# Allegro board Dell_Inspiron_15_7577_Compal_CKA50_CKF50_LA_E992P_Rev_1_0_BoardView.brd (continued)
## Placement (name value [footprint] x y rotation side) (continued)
PC5588  .1U_0402_16V7K  [C_0402]  173.48 108.23 180 bottom
PC5589  .1U_0402_16V7K  [C_0402]  173.49 107.31 180 bottom
PC5590  1U_0402_6.3V6K  [C_0402]  150.87 98.08 0 top
PC5591  1U_0402_6.3V6K  [C_0402]  146.68 98.14 0 top
PC5592  1U_0402_6.3V6K  [C_0402]  146.68 97.2 0 top
PC5593  1U_0402_6.3V6K  [C_0402]  150.54 87.67 0 top
PC5594  1U_0402_6.3V6K  [C_0402]  148.7 87.62 0 top
PC5595  1U_0402_6.3V6K  [C_0402]  148.71 98.08 0 top
PC5596  .1U_0402_16V7K  [C_0402]  148.71 97.14 0 top
PC5597  .1U_0402_16V7K  [C_0402]  158.05 87.62 0 top
PC5598  .1U_0402_16V7K  [C_0402]  156.2 87.62 0 top
PC5599  .1U_0402_16V7K  [C_0402]  157.22 98.14 0 top
PC5600  .1U_0402_16V7K  [C_0402]  152.97 97.14 0 top
PC5601  .1U_0402_16V7K  [C_0402]  152.45 87.7 0 top
PC5602  .1U_0402_16V7K  [C_0402]  154.35 87.69 0 top
PC5603  .1U_0402_16V7K  [C_0402]  157.22 97.14 0 top
PC5604  .1U_0402_16V7K  [C_0402]  152.97 98.08 0 top
PC5605  .1U_0402_16V7K  [C_0402]  159.19 98.8 0 top
PC5606  .1U_0402_16V7K  [C_0402]  159.19 97.72 0 top
PC5607  .1U_0402_16V7K  [C_0402]  155.12 97.14 0 top
PC5608  .1U_0402_16V7K  [C_0402]  155.12 98.14 0 top
PC5609  .1U_0402_16V7K  [C_0402]  146.73 87.69 0 top
PC5610  .1U_0402_16V7K  [C_0402]  150.87 97.14 0 top
PC6000  0.1U_0402_25V6  [C_0402]  152.19 136.6 90 top
PC6002  0.01U_0402_16V7K  [C_0402]  153.06 136.73 0 top
PC6006  0.015U_0402_16V7K  [C_0402]  153.52 135.08 90 bottom
PC6007  0.12U_0402_10V6K  [C_0402]  149.53 142.49 90 top
PC6008  0.1U_0402_25V6  [C_0402]  153.06 134.93 0 top
PC6009  0.1U_0402_10V6K  [C_0402]  150.36 144.31 0 top
PC6011  0.1U_0402_25V6  [C_0402]  152.92 132.67 90 top
PC6014  1U_0402_6.3V6K  [C_0402]  161.32 142.65 0 top
PC6015  4700P_0402_50V7K  [C_0402]  164.36 135.6 0 top
PC6016  0.01U_0402_16V  [C_0402]  163.5 137.43 180 top
PC6100  1U_0603_16V7  [C_0603]  170.41 131.16 180 bottom
PC6101  1U_0603_16V7  [C_0603]  177.52 128.87 90 top
PC6102  0.1U_0603_50V7K  [C_0603]  170.09 133.25 0 bottom
PC6103  10U_0805_25V6K~D  [C_0805]  172.84 134.39 180 top
PC6104  10U_0805_25V6K~D  [C_0805]  172.84 136.11 180 top
PC6105  10U_0805_25V6K~D  [C_0805]  173.6 143.44 0 top
PC6106  100U_25V_M  [C_ECST250ADA101MF611]  164.6 141.32 0 bottom
PC6107  470U_D2_2VM_R4.5M~D  [C_D1]  189.14 130.9 0 bottom
PC6108  1U_0402_25V6K  [C_0402]  166.21 130.33 0 bottom
PC6109  1000P_0402_50V7K  [C_0402]  166.21 131.22 0 bottom
PC6110  0.1U_0402_25V6  [C_0402]  172.84 132.11 180 top
PC6111  2200P_0402_50V7K  [C_0402]  172.82 133.06 180 top
PC6112  10U_0805_25V6K~D  [C_0805]  173.94 135.98 0 bottom
PC6113  3300P_0805_50V7K  [C_0805]  178 132.81 0 top
PC6114  1U_0603_16V7  [C_0603]  170.03 139.99 180 bottom
PC6115  0.1U_0603_50V7K  [C_0603]  169.5 142.38 0 bottom
PC6116  1U_0603_16V7  [C_0603]  176.32 137.76 90 top
PC6117  0.1U_0402_25V6  [C_0402]  172.26 140.05 180 top
PC6118  2200P_0402_50V7K  [C_0402]  172.25 141 180 top
PC6119  10U_0805_25V6K~D  [C_0805]  172.44 142.38 180 top
PC6121  470U_D2_2VM_R4.5M~D  [C_D1]  191.49 116.11 90 bottom
PC6122  1U_0402_25V6K  [C_0402]  167.74 142.65 0 top
PC6123  1000P_0402_50V7K  [C_0402]  167.74 143.54 0 top
PC6124  10U_0805_25V6K~D  [C_0805]  173.99 135.98 0 top
PC6125  10U_0805_25V6K~D  [C_0805]  177.72 144.71 180 bottom
PC6126  10U_0805_25V6K~D  [C_0805]  175.59 123.42 0 top
PC6127  3300P_0805_50V7K  [C_0805]  179.13 142.28 270 top
PC6128  1U_0603_16V7  [C_0603]  171.69 117.86 90 bottom
PC6129  0.1U_0603_50V7K  [C_0603]  171.79 121.28 0 bottom
PC6130  1U_0603_16V7  [C_0603]  176.44 115.15 180 bottom
PC6131  1U_0402_25V6K  [C_0402]  176.49 126.46 0 top
PC6132  1000P_0402_50V7K  [C_0402]  167.09 139.98 0 top
PC6133  0.1U_0402_25V6  [C_0402]  167.1 140.96 0 top
PC6134  2200P_0402_50V7K  [C_0402]  176.49 127.35 0 top
PC6135  10U_0805_25V6K~D  [C_0805]  173.2 144.71 0 bottom
PC6136  10U_0805_25V6K~D  [C_0805]  175.59 125.12 0 top
PC6137  10U_0805_25V6K~D  [C_0805]  175.59 123.42 0 bottom
PC6138  10U_0805_25V6K~D  [C_0805]  175.59 125.12 0 bottom
PC6140  470U_D2_2VM_R4.5M~D  [C_D1]  188.94 135.66 0 bottom
PC6141  3300P_0805_50V7K  [C_0805]  179.81 118.87 90 top
PC6500  1U_0402_6.3V6K  [C_0402]  215.71 91.91 180 top
PC6501  1U_0402_6.3V6K  [C_0402]  215.71 93.31 180 top
PC6502  1U_0402_6.3V6K  [C_0402]  212.57 105.18 180 top
PC6503  1U_0402_6.3V6K  [C_0402]  210.99 106.58 0 top
PC6504  1U_0402_6.3V6K  [C_0402]  224.46 96.8 180 top
PC6505  1U_0402_6.3V6K  [C_0402]  217.48 91.91 180 top
PC6506  1U_0402_6.3V6K  [C_0402]  213.39 105.18 0 top
PC6507  1U_0402_6.3V6K  [C_0402]  217.36 90.51 180 top
PC6508  1U_0402_6.3V6K  [C_0402]  215.57 90.51 180 top
PC6509  1U_0402_6.3V6K  [C_0402]  212.88 90.52 0 top
PC6510  1U_0402_6.3V6K  [C_0402]  213.03 91.91 0 top
PC6511  1U_0402_6.3V6K  [C_0402]  220.12 93.31 0 top
PC6512  1U_0402_6.3V6K  [C_0402]  218.34 93.31 0 top
PC6513  1U_0402_6.3V6K  [C_0402]  217.48 93.31 180 top
PC6514  1U_0402_6.3V6K  [C_0402]  223.25 91.91 180 top
PC6515  1U_0402_6.3V6K  [C_0402]  223 93.31 180 top
PC6516  1U_0402_6.3V6K  [C_0402]  213.03 93.31 0 top
PC6517  1U_0402_6.3V6K  [C_0402]  213.03 94.7 0 top
PC6518  1U_0402_6.3V6K  [C_0402]  215.71 94.7 180 top
PC6519  1U_0402_6.3V6K  [C_0402]  227.76 93.95 270 top
PC6520  1U_0402_6.3V6K  [C_0402]  210.78 105.31 270 top
PC6521  1U_0402_6.3V6K  [C_0402]  197.54 112.64 180 top
PC6522  1U_0402_6.3V6K  [C_0402]  215.63 105.18 0 top
PC6523  1U_0402_6.3V6K  [C_0402]  210.36 108.03 90 top
PC6524  1U_0402_6.3V6K  [C_0402]  208.24 110.01 90 top
PC6525  1U_0402_6.3V6K  [C_0402]  204.38 113.36 90 top
PC6526  1U_0402_6.3V6K  [C_0402]  201.14 110.91 270 top
PC6527  1U_0402_6.3V6K  [C_0402]  215.8 98.14 0 top
PC6528  1U_0402_6.3V6K  [C_0402]  215.8 96.8 0 top
PC6529  1U_0402_6.3V6K  [C_0402]  209.47 109.87 90 top
PC6530  1U_0402_6.3V6K  [C_0402]  205.27 113.36 90 top
PC6531  1U_0402_6.3V6K  [C_0402]  203.49 113.36 90 top
PC6532  1U_0402_6.3V6K  [C_0402]  212.81 96.8 0 top
PC6533  1U_0402_6.3V6K  [C_0402]  210.55 98.2 180 top
PC6534  1U_0402_6.3V6K  [C_0402]  223.55 90.52 0 top
PC6535  1U_0402_6.3V6K  [C_0402]  223.95 88.49 180 top
PC6536  1U_0402_6.3V6K  [C_0402]  221.28 88.49 0 top
PC6537  1U_0402_6.3V6K  [C_0402]  222.68 89.82 180 top
PC6538  1U_0402_6.3V6K  [C_0402]  220 89.88 0 top
PC6539  1U_0402_6.3V6K  [C_0402]  218.22 89.88 0 top
PC6540  1U_0402_6.3V6K  [C_0402]  216.69 88.42 0 top
PC6541  1U_0402_6.3V6K  [C_0402]  211.96 88.35 180 top
PC6542  1U_0402_6.3V6K  [C_0402]  210.3 90.52 180 top
PC6543  1U_0402_6.3V6K  [C_0402]  210.37 91.91 180 top
PC6544  1U_0402_6.3V6K  [C_0402]  210.37 93.31 180 top
PC6545  1U_0402_6.3V6K  [C_0402]  210.37 94.7 180 top
PC6546  1U_0402_6.3V6K  [C_0402]  211.24 91.91 0 top
PC6547  1U_0402_6.3V6K  [C_0402]  211.24 93.31 0 top
PC6548  1U_0402_6.3V6K  [C_0402]  211.24 94.7 0 top
PC6549  1U_0402_6.3V6K  [C_0402]  224.47 103.09 180 top
PC6550  1U_0402_6.3V6K  [C_0402]  225.29 96.8 0 top
PC6551  1U_0402_6.3V6K  [C_0402]  225.32 104.49 0 top
PC6552  1U_0402_6.3V6K  [C_0402]  220.12 91.91 0 top
PC6553  1U_0402_6.3V6K  [C_0402]  224.46 98.2 180 top
PC6554  1U_0402_6.3V6K  [C_0402]  224.46 104.49 180 top
PC6555  1U_0402_6.3V6K  [C_0402]  212.05 90.52 180 top
PC6556  1U_0402_6.3V6K  [C_0402]  225.32 98.2 0 top
PC6557  1U_0402_6.3V6K  [C_0402]  218.34 91.91 0 top
PC6558  1U_0402_6.3V6K  [C_0402]  224.46 100.29 180 top
PC6559  1U_0402_6.3V6K  [C_0402]  224.47 101.69 180 top
PC6560  1U_0402_6.3V6K  [C_0402]  225.32 101.69 0 top
PC6561  1U_0402_6.3V6K  [C_0402]  225.35 100.29 0 top
PC6562  1U_0402_6.3V6K  [C_0402]  221.45 94.64 0 top
PC6563  1U_0402_6.3V6K  [C_0402]  220.59 94.64 180 top
PC6564  1U_0402_6.3V6K  [C_0402]  225.32 103.09 0 top
PC6565  10U_0603_6.3V6M  [C_0603]  197.09 121.82 90 bottom
PC6566  10U_0603_6.3V6M  [C_0603]  195.82 121.82 90 bottom
PC6567  10U_0603_6.3V6M  [C_0603]  194.55 121.82 90 bottom
PC6568  10U_0603_6.3V6M  [C_0603]  224.19 93.25 0 top
PC6569  10U_0603_6.3V6M  [C_0603]  224.19 94.45 0 top
PC6570  10U_0603_6.3V6M  [C_0603]  218.61 94.52 180 top
PC6571  10U_0603_6.3V6M  [C_0603]  217.79 98.2 270 top
PC6572  10U_0603_6.3V6M  [C_0603]  214.74 98.2 270 top
PC6573  10U_0603_6.3V6M  [C_0603]  211.79 98.2 270 top
PC6574  10U_0603_6.3V6M  [C_0603]  196.32 111.85 180 bottom
PC6575  10U_0603_6.3V6M  [C_0603]  196.32 113.12 180 bottom
PC6576  10U_0603_6.3V6M  [C_0603]  196.32 114.39 180 bottom
PC6577  10U_0603_6.3V6M  [C_0603]  196.32 115.66 180 bottom
PC6578  10U_0603_6.3V6M  [C_0603]  224.19 92.04 0 top
PC6579  10U_0603_6.3V6M  [C_0603]  198.42 121.82 90 bottom
PC6580  22U_0805_6.3VAM  [C_0805]  202.48 111.53 270 top
PC6581  22U_0805_6.3VAM  [C_0805]  204.2 110.35 270 top
PC6582  22U_0805_6.3VAM  [C_0805]  206.3 108.24 270 top
PC6583  22U_0805_6.3VAM  [C_0805]  208.44 106.03 270 top
PC6584  47U_0805_6.3V6M  [C_0805]  196.47 117.19 180 bottom
PC6585  47U_0805_6.3V6M  [C_0805]  206.92 110.18 90 top
PC6586  47U_0805_6.3V6M  [C_0805]  199.81 111.19 270 top
PC6587  330U_D3_2VM_R6M  [C_D3]  188.86 130.84 0 top
PC6588  470U_D2_2VM_R4.5M~D  [C_D1]  189.13 126.14 0 bottom
PC6589  330U_D3_2VM_R6M  [C_D3]  220.77 97.32 90 top
PD1  -  [L30ESD24VC3-2_SOT23-3]  45.92 50.24 90 top
PD3  -  [TVNST52302AB0_SOT523-3]  62.35 29.62 270 top
PD4  -  [TVNST52302AB0_SOT523-3]  62.35 27.59 270 top
PD700  -  [BAT54CW_SOT323-3]  41.13 43.32 270 bottom
PH5000  470K_0402_5%_B25/50 4700K  [R_0402]  122.66 123.71 90 bottom
PH5001  10K +-5% 0402 B25/50 4250K  [R_0402]  164.77 117.12 180 bottom
PH5002  10K +-5% 0402 B25/50 4250K  [R_0402]  127.56 127.51 180 bottom
PH5003  10K +-5% 0402 B25/50 4250K  [R_0402]  155.61 118.25 90 bottom
PH5004  470K_0402_5%_B25/50 4700K  [R_0402]  147.93 129.56 90 bottom
PH6000  470K_0402_5%_B25/50 4700K  [R_0402]  148.6 145.25 0 top
PJP10V0  -  [JUMP_43X39]  115.04 98.72 270 bottom
PJP10V1  -  [JUMP_43X79]  125.52 88.46 270 bottom
PJP11  -  [JUMP_43X79]  253.86 48.35 180 top
PJP12  -  [JUMP_43X118]  264.6 38.95 0 bottom
PJP18V1  -  [JUMP_43X39]  277.17 73.82 180 bottom
PJP18V2  -  [JUMP_43X79]  267.04 88.29 180 bottom
PJP25V1  -  [JUMP_43X79]  176.02 26.07 180 bottom
PJP25V2  -  [JUMP_43X79]  166.22 24.54 270 bottom
PJP31  -  [JUMP_43X118]  75.5 35.97 0 bottom
PJP32  -  [JUMP_43X118]  75.54 30.64 0 bottom
PJP33  -  [JUMP_43X118]  68.87 53.5 0 bottom
PJP34  -  [JUMP_43X118]  69.83 48.16 0 bottom
PJP200  -  [JUMP_43X39]  101.09 67.92 0 top
PJP201  -  [JUMP_43X118]  120.18 73.56 270 top
PJP202  -  [JUMP_43X118]  120.18 73.56 270 bottom
PJP203  -  [JUMP_43X39]  104.37 66.08 270 top
PJP801  -  [JUMP_43X118]  255.26 65.74 90 bottom
PJP802  -  [JUMP_43X118]  260.68 65.74 90 bottom
PJP1302  PAD-OPEN 43X39  [JUMP_43X39]  289.65 47.08 270 top
PJP1303  PAD-OPEN 43X39  [JUMP_43X39]  295.64 46.46 270 top
PJP1304  -  [JUMP_43X39]  267.96 17.87 180 bottom
PJP4000  -  [JUMP_43X39]  123.29 108.69 270 bottom
PJP4001  -  [JUMP_43X118]  130.66 91 270 bottom
PJPDC1  ACES_51202-00901-001  [ACES_51202-00901-001_9P-T]  29.04 54.02 315 bottom
PL1  HCB2012KF-121T50_2P  [TAI-T_HCB2012KF-121T50_2P]  53.57 60.47 270 bottom
PL2  HCB2012KF-121T50_2P  [TAI-T_HCB2012KF-121T50_2P]  49.95 60.47 270 bottom
PL3  BLM15HG601SN1D_2P  [MURAT_BLM15HG601SN1D_2P]  44.18 52.81 0 top
PL4  HCB2012KF-121T50_0805  [TAI-T_HCB2012KF-121T50_2P]  55.3 37.64 270 bottom
PL5  HCB2012KF-121T50_0805  [TAI-T_HCB2012KF-121T50_2P]  53.51 37.64 270 bottom
PL6  HCB2012KF-121T50_2P  [TAI-T_HCB2012KF-121T50_2P]  51.77 60.45 270 bottom
PL7  HCB2012KF-121T50_2P  [TAI-T_HCB2012KF-121T50_2P]  51.77 60.46 270 top
PL8  HCB2012KF-121T50_2P  [TAI-T_HCB2012KF-121T50_2P]  49.95 60.47 270 top
PL9  HCB2012KF-121T50_2P  [TAI-T_HCB2012KF-121T50_2P]  53.57 60.47 270 top
PL10V0  1UH_1239AS-H-1R0M-P2_3A_20%  [TOKO_1239AS-H-1R0M-P2_2P]  120 91.66 180 bottom
PL10V01  3A_Z120_40M_0603_2P  [C_0603]  116.84 97.75 0 bottom
PL18V00  1UH_PCMB042T-1R0MS_4.5A_20%  [CYNTE_PCMB042T-1R0MS_2P]  271.7 83.78 180 bottom
PL100  1UH_PCMB063T-1R0MS_12A_20%  [CYNTE_PCMB063T-1R0MS_2P]  255.27 45.38 0 bottom
PL200  1UH_11A_20%_7X7X3_M  [L_7X7X3_M_2P]  113.77 82.07 270 bottom
PL300  HCB2012KF-121T50_0805  [TAI-T_HCB2012KF-121T50_2P]  77.53 36.62 180 top
PL301  HCB2012KF-121T50_0805  [TAI-T_HCB2012KF-121T50_2P]  77.55 38.39 180 top
PL302  S COIL 1.5UH +-20% 9A 7X7X3  [L_7X7X3_M_2P]  60.29 45.94 0 bottom
PL303  S COIL 1.5UH +-20% 9A 7X7X3  [L_7X7X3_M_2P]  66.27 37.94 180 bottom
PL700  HCB3225KF-151T50_2P  [KC_FBMA-L11-322513151LMA50T_2P]  39.44 37.11 0 bottom
PL701  4.7UH_MMD-10DZ-4R7M-X2_9.5A_20%  [MAG_MMD-10DZ-4R7M-X2_2P]  46.42 43.53 0 bottom
PL800  FBMA-L11-453215800LMA90T_2P  [KC_FBMA-L11-453215800LMA90T_2P]  244.64 58.58 90 top
PL801  0.88UH_PCMC104T-R88MN_20A_20%  [CYNTE_PCMC104T-R88MN_2P]  255.6 54.38 0 bottom
PL4000  1UH_PCMB042T-1R0MS_4.5A_20%  [CYNTE_PCMB042T-1R0MS_2P]  125 97.12 0 bottom
PL5100  FBMA-L11-453215800LMA90T_2P  [KC_FBMA-L11-453215800LMA90T_2P]  119.5 111.86 0 bottom
PL5101  0.15UH_PCME064T-R15MS0R667_36A_20%  [CYNTE_PCME064T-R15MS0R667_2P]  151.37 114.33 90 bottom
PL5102  0.15UH_PCME064T-R15MS0R667_36A_20%  [CYNTE_PCME064T-R15MS0R667_2P]  143.13 114.2 90 bottom
PL5103  0.15UH_PCME064T-R15MS0R667_36A_20%  [CYNTE_PCME064T-R15MS0R667_2P]  159.88 114.41 90 bottom
PL5201  0.15UH_PCME064T-R15MS0R667_36A_20%  [CYNTE_PCME064T-R15MS0R667_2P]  131.55 123.59 180 bottom
PL5202  0.15UH_PCME064T-R15MS0R667_36A_20%  [CYNTE_PCME064T-R15MS0R667_2P]  131.6 131.44 180 bottom
PL5203  0.47UH_MMD05CZR47M_12A_20%  [MAG_MMD05CZR47M_4P]  167.97 119.64 270 bottom
PL6100  FBMA-L11-453215800LMA90T_2P  [KC_FBMA-L11-453215800LMA90T_2P]  166.6 132.81 90 bottom
PL6101  0.22UH_MMD-06DZER22MEM2L__32A_20%  [L_7X7X4_M]  183.17 126.48 90 bottom
PL6102  0.22UH_MMD-06DZER22MEM2L__32A_20%  [L_7X7X4_M]  182.92 142.69 270 bottom
PL6103  0.22UH_MMD-06DZER22MEM2L__32A_20%  [L_7X7X4_M]  185.01 121.23 270 bottom
PQ1  FDV301N_G 1N SOT23-3  [FDV301N_NL_SOT23-3]  44.74 54.68 0 top
PQ2  S TR METR3904W-G NPN SOT323-3  [RHU002N06_SOT323-3]  41.31 54.41 0 top
PQ5  L2N7002WT1G 1N SC-70-3  [SSM3K7002FU_SC70-3]  64.9 25.52 0 top
PQ6  -  [DMN65D8LDW-7_SOT363-6]  51.1 27.07 0 top
PQ7  -  [DMN65D8LDW-7_SOT363-6]  54.95 27.08 0 top
PQ8  L2N7002WT1G 1N SC-70-3  [SSM3K7002FU_SC70-3]  34.39 48.04 0 top
PQ9  L2N7002WT1G 1N SC-70-3  [SSM3K7002FU_SC70-3]  61.48 23.5 90 top
PQ201  -  [AON7408L_DFN8-5]  106.27 75.82 180 top
PQ202  -  [AON7506_DFN33-8-5]  108.03 73.14 0 top
PQ301  -  [AON7380_DFN3X3-8-5]  72.01 49.41 270 top
PQ302  -  [AON6796_DFN5X6-8-5]  65.89 43.71 0 top
PQ303  -  [AON7380_DFN3X3-8-5]  71.66 34.85 270 top
PQ304  -  [AON6796_DFN5X6-8-5]  69.64 38.45 180 top
PQ305  -  [L2N7002WT1G_SC70-3]  83.67 51.46 90 top
PQ700  L2N7002WT1G 1N SC-70-3  [SSM3K7002FU_SC70-3]  54.84 25.24 90 top
PQ701  -  [AON6366E_DFN5X6-8-5]  54.84 54.83 270 bottom
PQ702  -  [AON6366E_DFN5X6-8-5]  54.84 49.88 90 top
PQ703  -  [AON6366E_DFN5X6-8-5]  54.9 43.78 90 top
PQ704  -  [AON7506_DFN33-8-5]  53.51 38.7 270 top
PQ705  -  [AON6380_DFN5X6-8-5]  46.78 42.19 90 top
PQ706  L2N7002WT1G 1N SC-70-3  [SSM3K7002FU_SC70-3]  39.45 32.27 270 top
PQ707  -  [AON7380_DFN3X3-8-5]  44.62 40.15 270 top
PQ708  L2N7002WT1G 1N SC-70-3  [SSM3K7002FU_SC70-3]  31.93 48.02 0 top
PQ800  -  [AON6992_DFN5X6D-8-7]  257.4 58.04 180 top
PQ801  -  [AON6992_DFN5X6D-8-7]  251.25 58.04 180 top
PQ802  -  [BSS138W_SOT323-3]  236.77 51.08 90 top
PQ6000  DMN53D0LDW-7 2N SOT363-6  [2N7002DW-7-F_SOT363-6]  166.36 132.93 180 top
PR1  33_0402_5%  [R_0402]  43.8 58.51 180 top
PR2  2.2K_0402_5%  [R_0402]  41.96 58.51 180 top
PR3  100K_0402_1%  [R_0402]  40.41 51.73 0 top
PR4  10K_0402_1%  [R_0402]  43.28 53.81 180 top
PR5  15K_0402_1%  [R_0402]  41.33 52.7 180 top
PR8  100_0402_1%  [R_0402]  59.08 30.13 0 top
PR10  100_0402_1%  [R_0402]  59.08 29.17 0 top
PR10V0  4.7_0603_5%  [R_0603]  122.15 95.6 0 bottom
PR10V1  10K_0402_5%  [R_0402]  123.05 94.53 180 bottom
PR10V2  6.81K_0402_1%  [R_0402]  114.91 92.62 270 bottom
PR10V3  10K_0402_1%  [R_0402]  115.88 93.56 180 bottom
PR10V4  0_0402_5%  [R0402_0OHM]  122.91 92.67 180 bottom
PR10V5  1M_0402_1%  [R_0402]  122.02 90.9 0 bottom
PR10V6  0_0402_5%  [R_0402]  122.92 93.56 180 bottom
PR12  100_0402_1%  [R_0402]  59.08 28.16 0 top
PR13  10K_0402_1%  [R_0402]  60 27.07 180 top
PR15  3.3K_0402_1%  [R_0402]  51.74 30.23 180 top
PR16  1M_0402_1%  [R_0402]  53.56 26.98 90 top
PR18V00  0_0402_5%  [R0402_0OHM]  266.66 75.85 0 bottom
PR18V01  0_0603_5%  [R_0603]  273.34 80.86 90 top
PR18V02  20.5K_0402_1%  [R_0402]  266.52 81.27 0 bottom
PR18V03  4.7_0603_5%  [R_0603]  271.12 83.4 0 top
PR18V04  1M_0402_1%  [R_0402]  267.58 76.74 180 bottom
PR18V05  10K_0402_1%  [R_0402]  267.58 79.4 180 bottom
PR18V06  0_0402_5%  [R_0402]  268.83 79.15 90 top
PR18V07  0_0402_5%  [R0402_0OHM]  266.54 78.51 0 bottom
PR20  200K_0402_1%  [R_0402]  48.54 27.59 0 top
PR21  100K_0402_1%  [R_0402]  65.44 29.53 270 top
PR22  1M_0402_1%  [R_0402]  50.89 26 0 top
PR23  1M_0402_1%  [R_0402]  56.48 30.19 0 top
PR24  0_0402_5%  [R0402_0OHM]  26.4 37.58 0 top
PR25  0_0402_5%  [R0402_0OHM]  27.32 36.69 180 top
PR25V00  0_0402_5%  [R0402_0OHM]  175.93 32.3 270 bottom
PR25V01  1M_0402_1%  [R_0402]  174.16 31.38 90 bottom
PR25V02  100K_0402_1%  [R_0402]  173.03 31.84 180 bottom
PR25V03  21.5K_0402_1%  [R_0402]  164.82 29.56 0 bottom
PR25V04  10K_0402_1%  [R_0402]  164.81 30.52 0 bottom
PR26  14.3K_0402_1%  [R_0402]  27.32 35.8 180 top
PR27  10K_0402_1%  [R_0402]  26.4 34.85 0 top
PR28  10K_0402_1%  [R_0402]  35.28 46.01 90 top
PR29  12.4K_0402_1%  [R_0402]  36.36 47.07 270 top
PR30  160K_0402_1%  [R_0402]  36.36 47.89 90 top
PR31  1M_0402_1%  [R_0402]  54.7 30.19 0 top
PR32  10K_0402_5%  [R_0402]  58.23 27.08 180 top
PR33  100K_0402_1%  [R_0402]  55.17 26.13 0 top
PR34  0_0402_5%  [R0402_0OHM]  63.73 23.43 180 top
PR35  100K_0402_1%  [R_0402]  58.41 23.31 90 top
PR101  0_0402_5%  [R0402_0OHM]  252.01 43.32 90 top
PR102  1M_0402_1%  [R_0402]  250.23 37.25 270 top
PR103  0_0402_5%  [R0402_0OHM]  249.34 36.34 90 top
PR104  4.7_1206_5%  [R_1206]  254.74 40.8 0 top
PR106  14K_0402_1%  [R_0402]  252.07 36.34 90 top
PR107  20K_0402_1%  [R_0402]  253.09 35.92 270 bottom
PR108  0_0402_5%  [R_0402]  254.13 38.43 0 top
PR109  0_0402_5%  [R_0402]  255.06 38.46 270 bottom
PR200  2.2_0603_5%  [R_0603]  107.94 69.19 270 top
PR201  20.5K_0402_1%  [R_0402]  111.86 71.2 270 top
PR202  4.7_1206_5%  [R_1206]  107.83 75.26 90 bottom
PR203  5.1_0603_5%  [R_0603]  111.87 71.95 270 bottom
PR204  2.2_0603_5%  [R_0603]  113.02 71.67 270 top
PR205  12K_0402_1%  [R_0402]  113.64 64.14 180 top
PR206  100K_0402_1%  [R_0402]  115.43 71.09 270 top
PR207  453K_0402_1%  [R_0402]  115.7 68.74 180 top
PR208  20K_0402_1%  [R_0402]  113.66 63.2 180 top
PR209  0_0402_5%  [R0402_0OHM]  115.7 66.84 180 top
PR210  0_0402_5%  [R_0402]  115.7 64.93 180 top
PR211  0_0402_5%  [R0402_0OHM]  115.7 65.89 180 top
PR300  6.49K_0402_1%  [R_0402]  85.31 44.75 270 top
PR301  15.4K_0402_1%  [R_0402]  85.5 41.77 270 top
PR302  10K_0402_1%  [R_0402]  84.42 44.75 270 top
PR303  10K_0402_1%  [R_0402]  84.61 41.77 270 top
PR304  6.19K_0402_1%  [R_0402]  85.32 45.69 180 top
PR305  16.5K_0402_1%  [R_0402]  83.61 39.07 90 top
PR306  200_0402_1%  [R_0402]  82.14 39.66 270 top
PR307  0_0603_5%  [R_0603]  80.8 47.85 270 top
PR308  0_0603_5%  [R_0603]  80.16 39.22 270 top
PR309  4.7_1206_5%  [R_1206]  63.16 48.48 270 top
PR310  4.7_1206_5%  [R_1206]  62.02 37.3 90 top
PR311  0_0402_5%  [R0402_0OHM]  84.81 48.72 90 top
PR312  0_0402_5%  [R0402_0OHM]  82.91 48.72 90 top
PR313  2.2K_0402_5%  [R_0402]  83.86 48.72 90 top
PR314  100K_0402_1%  [R_0402]  84.41 47.15 0 top
PR315  0_0402_5%  [R0402_0OHM]  81.95 48.72 90 top
PR700  3M_0402_5%  [R_0402]  50.89 24.09 0 top
PR701  1M_0402_1%  [R_0402]  50.89 25.05 0 top
PR702  4.7_0402_5%  [R_0402]  54.66 49.48 180 bottom
PR703  0.005_1206_1%  [R_1206_4P-D]  53.37 41.24 0 top
PR704  4.7_0402_5%  [R_0402]  55.49 55.27 180 top
PR705  0_0402_5%  [R0402_0OHM]  37.36 43.62 90 top
PR706  0_0402_5%  [R0402_0OHM]  38.25 43.62 90 top
PR707  4.02K_0402_1%  [R_0402]  51.04 36.67 180 top
PR708  10_0402_1%  [R_0402]  51.04 37.62 180 top
PR709  4.12K_0603_1%  [R_0603]  35.1 44.45 270 top
PR710  4.12K_0603_1%  [R_0603]  36.31 44.46 270 top
PR711  10_1206_1%  [R_1206]  39.4 42.62 270 bottom
PR712  2.2_0603_5%  [R_0603]  40.23 38.51 180 top
PR713  7.5K_0402_1%  [R_0402]  38 33.49 0 top
PR714  20K_0402_1%  [R_0402]  38.91 34.45 180 top
PR715  5.76K_0402_1%  [R_0402]  38 35.4 0 top
PR716  0.01_1206_1%  [R_1206_4P-D]  43.56 36.4 0 bottom
PR717  4.7_1206_5%  [R_1206]  47.73 36.24 180 top
PR718  100K_0402_1%  [R_0402]  34.28 43.87 270 bottom
PR719  120K_0402_5%  [R_0402]  33.4 42.96 90 bottom
PR720  324K_0402_1%  [R_0402]  34.01 46.93 270 top
PR721  0_0402_5%  [R0402_0OHM]  29.62 42.45 0 top
PR722  10K_0402_1%  [R_0402]  38.01 31.64 90 top
PR723  0_0402_5%  [R0402_0OHM]  32 33.57 90 top
PR724  10_0402_1%  [R_0402]  35.98 34.69 270 top
PR725  49.9K_0402_1%  [R_0402]  34.02 44.41 180 top
PR726  10_0402_1%  [R_0402]  35.12 34.69 270 top
PR727  0_0402_5%  [R0402_0OHM]  31.98 39.64 90 bottom
PR728  0_0402_5%  [R_0402]  29.62 39.69 0 top
PR729  0_0402_5%  [R_0402]  31.97 37.9 90 bottom
PR730  0_0402_5%  [R0402_0OHM]  29.62 38.68 0 top
PR731  0_0402_5%  [R0402_0OHM]  29.62 37.79 0 top
PR732  0_0402_5%  [R0402_0OHM]  29.62 36.9 0 top
PR733  0_0402_5%  [R0402_0OHM]  29.62 36.03 0 top
PR734  100K_0402_1%  [R_0402]  32.37 51.13 180 top
PR800  100K_0402_1%  [R_0402]  234.09 57.85 0 top
PR801  2.2_0603_5%  [R_0603]  241.53 56.8 0 top
PR802  42.2K_0402_1%  [R_0402]  234.09 56.85 0 top
PR803  20K_0402_1%  [R_0402]  234.09 55.84 0 top
PR804  470K_0402_1%  [R_0402]  237.64 52.9 0 top
PR805  4.7_1206_5%  [R_1206]  259.27 54.96 270 top
PR807  9.76K_0402_1%  [R_0402]  234.54 53.11 270 top
PR809  10.5K_0402_1%  [R_0402]  235 54.07 180 top
PR810  1K_0402_1%  [R_0402]  232.75 51.34 0 top
PR811  100K_0402_1%  [R_0402]  233.67 50.45 180 top
PR812  47.5K_0402_1%  [R_0402]  235.89 52.9 0 top
PR813  100_0402_1%  [R_0402]  232.76 52.23 0 top
PR814  0_0402_5%  [R0402_0OHM]  233.67 53.1 180 top
PR815  49.9_0402_1%  [R_0402]  234.54 50.43 90 top
PR4000  0_0603_5%  [R_0603]  121.51 102.26 270 bottom
PR4001  10K_0402_5%  [R_0402]  125.52 106.78 270 bottom
PR4002  4.7_1206_5%  [R_1206]  123.17 98.14 180 bottom
PR4003  0_0402_5%  [R0402_0OHM]  128.25 106.58 270 bottom
PR4004  10_0402_1%  [R_0402]  129.88 101.97 90 bottom
PR4005  1M_0402_1%  [R_0402]  127.31 105.62 90 bottom
PR4006  21K_0402_1%  [R_0402]  128.97 102.87 180 bottom
PR4007  0_0402_5%  [R0402_0OHM]  130.77 102.83 0 bottom
PR4008  0_0402_5%  [R_0402]  128.04 104.68 0 bottom
PR4009  35.7K_0402_1%  [R_0402]  128.04 101.06 0 bottom
PR4010  0_0402_5%  [R0402_0OHM]  132.55 102.62 0 bottom
PR4011  0_0402_5%  [R_0402]  128.96 103.74 180 bottom
PR5000  0_0402_5%  [R0402_0OHM]  135.23 144.38 270 bottom
PR5001  45.3_0402_1%  [R_0402]  136.18 143.46 90 bottom
PR5002  75_0402_1%  [R_0402]  137.07 143.46 90 bottom
PR5003  100_0402_1%  [R_0402]  139.84 143.58 90 bottom
PR5004  1_0402_5%  [R_0402]  138.01 144.48 270 bottom
PR5005  0_0402_5%  [R0402_0OHM]  138.93 143.56 90 bottom
PR5006  0_0402_5%  [R0402_0OHM]  135.23 144.38 270 top
PR5007  49.9_0402_1%  [R_0402]  136.18 144.38 270 top
PR5008  0_0402_5%  [R0402_0OHM]  138 144.48 270 top
PR5009  0_0402_5%  [R0402_0OHM]  137.07 144.38 270 top
PR5010  97.6K_0402_1%  [R_0402]  131.88 140.84 0 bottom
PR5011  0_0402_5%  [R0402_0OHM]  140.7 144.08 0 bottom
PR5012  10_0402_1%  [R_0402]  139.03 144.49 270 top
PR5013  27.4K_0402_1%  [R_0402]  129.15 141.91 90 top
PR5014  12.4K_0402_1%  [R_0402]  130.01 142.82 0 top
PR5015  1.91K_0402_1%  [R_0402]  133.26 144.22 270 top
PR5016  169K_0402_1%  [R_0402]  142.79 143.41 90 top
PR5017  16.9K_0402_1%  [R_0402]  141.83 143.41 90 top
PR5018  5.62K_0402_1%  [R_0402]  140.88 143.41 90 top
PR5019  110K_0402_1%  [R_0402]  139.93 143.58 90 top
PR5020  0_0402_5%  [R0402_0OHM]  134.21 144.22 270 top
PR5021  3.6K_0402_1%  [R_0402]  130.95 140.98 270 top
PR5022  2K_0402_1%  [R_0402]  130.03 139.1 180 top
PR5023  0_0402_5%  [R0402_0OHM]  133.26 144.22 270 bottom
PR5024  1.1K_0402_1%  [R_0402]  142.89 140.81 0 top
PR5025  1K_0402_1%  [R_0402]  129.13 137.27 0 top
PR5026  48.7K_0402_1%  [R_0402]  143.74 143.41 90 top
PR5027  1K_0402_1%  [R_0402]  143.88 140.45 90 bottom
PR5028  0_0402_5%  [R0402_0OHM]  130 143.71 0 top
PR5029  11K_0402_1%  [R_0402]  143 140.48 180 bottom
PR5030  3.6K_0402_1%  [R_0402]  163.86 118.01 0 bottom
PR5031  2.87K_0402_1%  [R_0402]  130 138.2 180 top
PR5032  316_0402_1%  [R_0402]  142.89 137.95 0 top
PR5033  2.74K_0402_1%  [R_0402]  142.89 137 0 top
PR5034  2.61K_0402_1%  [R_0402]  127.03 128.43 0 top
PR5035  11K_0402_1%  [R_0402]  132.8 139.95 180 bottom
PR5036  2K_0402_1%  [R_0402]  142.89 138.08 0 bottom
PR5037  4.53K_0402_1%  [R_0402]  142.88 137.1 0 bottom
PR5038  1K_0402_1%  [R_0402]  130.98 138.2 90 top
PR5039  110K_0402_1%  [R_0402]  142.89 136.11 0 bottom
PR5040  294_0402_1%  [R_0402]  131.92 138.2 0 top
PR5041  287_0402_1%  [R_0402]  139.97 133.58 270 top
PR5042  11K_0402_1%  [R_0402]  136.48 132.67 90 top
PR5043  1K_0402_1%  [R_0402]  139.19 132.68 0 bottom
PR5044  4.42K_0402_1%  [R_0402]  155.61 119.17 270 top
PR5045  12.4K_0402_1%  [R_0402]  136.46 130.85 90 top
PR5046  1K_0402_1%  [R_0402]  135.6 133.59 270 top
PR5047  93.1K_0402_1%  [R_0402]  132.83 136.3 180 top
PR5048  27.4K_0402_1%  [R_0402]  134.65 130.84 0 top
PR5049  2K_0402_1%  [R_0402]  134.63 133.58 270 bottom
PR5050  2.43K_0402_1%  [R_0402]  134.72 132.68 90 top
PR5051  3.65K_0402_1%  [R_0402]  136.49 133.59 270 bottom
PR5100  1_0402_5%  [R_0402]  151.18 129.75 90 bottom
PR5101  1_0402_5%  [R_0402]  147.11 128.9 270 top
PR5102  0_0402_5%  [R0402_0OHM]  149.39 130.65 270 bottom
PR5103  10K_0402_1%  [R_0402]  148.9 128.87 180 top
PR5104  0_0402_5%  [R0402_0OHM]  150.29 130.65 270 bottom
PR5105  2.2_0603_1%  [R_0603]  152.57 131.22 270 top
PR5106  10_1206_5%  [R_1206]  150.72 122.8 0 top
PR5107  3.65K_0603_1%  [R_0603]  149.39 119.6 0 top
PR5108  100K_0402_1%  [R_0402]  150.23 118.52 180 top
PR5109  10_0402_1%  [R_0402]  150.22 117.64 270 top
PR5110  20M_0402_5%  [R_0402]  148.38 120.31 270 top
PR5111  100K_0402_1%  [R_0402]  149.33 116.73 90 top
PR5112  100K_0402_1%  [R_0402]  148.44 117.11 90 top
PR5113  1_0402_5%  [R_0402]  136.06 128.65 270 top
PR5114  0_0402_5%  [R0402_0OHM]  139.99 130.47 270 bottom
PR5115  1_0402_5%  [R_0402]  141.9 129.56 90 bottom
PR5116  10K_0402_1%  [R_0402]  136.97 127.72 90 top
PR5117  0_0402_5%  [R0402_0OHM]  140.95 130.47 270 bottom
PR5118  2.2_0603_1%  [R_0603]  143.93 131.22 270 top
PR5119  3.65K_0603_1%  [R_0603]  143.61 120.36 180 top
PR5120  100K_0402_1%  [R_0402]  142.16 119.28 180 top
PR5121  10_1206_5%  [R_1206]  141.52 122.77 0 top
PR5122  10_0402_1%  [R_0402]  142.15 118.4 270 top
PR5123  100K_0402_1%  [R_0402]  141.26 117.49 90 top
PR5124  100K_0402_1%  [R_0402]  140.37 118.38 90 top
PR5125  1_0402_5%  [R_0402]  158.22 128.63 270 top
PR5126  0_0402_5%  [R0402_0OHM]  157.58 130.58 270 bottom
PR5127  1_0402_5%  [R_0402]  159.55 129.75 90 bottom
PR5128  10K_0402_1%  [R_0402]  157.31 127.72 90 top
PR5129  0_0402_5%  [R0402_0OHM]  158.48 130.57 270 bottom
PR5130  2.2_0603_1%  [R_0603]  161.2 131.22 270 top
PR5131  10_1206_5%  [R_1206]  159.61 122.9 0 top
PR5132  3.65K_0603_1%  [R_0603]  157.63 119.6 0 top
PR5133  100K_0402_1%  [R_0402]  158.48 118.52 180 top
PR5134  10_0402_1%  [R_0402]  158.47 117.64 270 top
PR5135  100K_0402_1%  [R_0402]  157.58 116.73 90 top
PR5136  100K_0402_1%  [R_0402]  156.69 116.73 90 top
PR5200  1_0402_5%  [R_0402]  116.27 118.95 180 bottom
PR5201  1_0402_5%  [R_0402]  118.02 114.94 0 top
PR5202  0_0402_5%  [R0402_0OHM]  115.43 117.07 0 bottom
PR5203  10K_0402_1%  [R_0402]  118.96 115.88 180 top
PR5204  0_0402_5%  [R0402_0OHM]  115.43 117.99 0 bottom
PR5205  2.2_0603_1%  [R_0603]  114.98 121.37 0 bottom
PR5206  4.7_1206_5%  [R_1206]  125.07 120.93 270 top
PR5207  3.65K_0603_1%  [R_0603]  124.75 122.33 0 top
PR5208  100K_0402_1%  [R_0402]  127.17 122.98 270 top
PR5209  10_0402_1%  [R_0402]  128.87 126.19 90 top
PR5210  20M_0402_5%  [R_0402]  135.12 138.27 180 bottom
PR5211  100K_0402_1%  [R_0402]  128.96 122.77 180 top
PR5212  1_0402_5%  [R_0402]  115.52 126.77 0 top
PR5213  0_0402_5%  [R0402_0OHM]  115.61 125.1 0 bottom
PR5214  1_0402_5%  [R_0402]  116.46 127.01 180 bottom
PR5215  0_0402_5%  [R0402_0OHM]  115.53 126.06 0 bottom
PR5216  10K_0402_1%  [R_0402]  116.32 128.04 180 top
PR5217  2.2_0603_1%  [R_0603]  114.91 129.39 0 bottom
PR5218  4.7_1206_5%  [R_1206]  125.64 132.87 270 top
PR5219  3.65K_0603_1%  [R_0603]  125.83 136.17 270 top
PR5220  100K_0402_1%  [R_0402]  126.98 134.7 90 top
PR5221  10_0402_1%  [R_0402]  129.74 135.6 270 top
PR5222  100K_0402_1%  [R_0402]  127.93 134.7 90 top
PR5223  0_0402_5%  [R0402_0OHM]  163.17 129.96 270 top
PR5224  0_0402_5%  [R0402_0OHM]  166.73 126.39 90 top
PR5225  2.2_0603_1%  [R_0603]  169.47 130.01 270 bottom
PR5226  4.7_1206_5%  [R_1206]  165.84 122.14 0 top
PR5227  3.65K_0603_1%  [R_0603]  168.5 118.05 180 top
PR5228  10_0402_1%  [R_0402]  167.34 116.97 0 top
PR5229  1_0402_5%  [R_0402]  164.06 129.05 90 top
PR5230  1_0402_5%  [R_0402]  166.73 124.6 90 top
PR5231  20M_0402_5%  [R_0402]  166.18 118.79 270 top
PR6000  100K_0402_5%  [R_0402]  154.42 136.87 180 bottom
PR6002  20K_0402_1%  [R_0402]  153.96 143.49 270 top
PR6003  20K_0402_1%  [R_0402]  154.85 143.61 270 top
PR6004  20K_0402_1%  [R_0402]  155.74 143.61 270 top
PR6006  910K_0402_5%  [R_0402]  153.06 137.65 0 top
PR6007  0_0402_5%  [R_0402]  148.62 142.5 90 top
PR6008  0_0402_5%  [R_0402]  148.6 144.31 0 top
PR6009  1_0402_1%  [R_0402]  152.12 144.35 90 top
PR6010  1_0402_1%  [R_0402]  153.91 144.36 180 top
PR6011  0_0402_5%  [R_0402]  150.42 142.48 90 top
PR6012  1_0402_1%  [R_0402]  153.91 145.25 180 top
PR6013  13.7K_0402_1%  [R_0402]  152.76 138.59 0 top
PR6017  2.4K_0402_1%  [R_0402]  154.41 135.08 90 bottom
PR6018  0_0402_5%  [R0402_0OHM]  153.07 135.81 0 top
PR6020  1K_0402_1%  [R_0402]  156.78 143.74 270 top
PR6021  0_0402_5%  [R0402_0OHM]  196.56 110.72 270 top
PR6022  0_0402_5%  [R_0402]  153.52 133.3 90 bottom
PR6023  100_0402_5%  [R_0402]  196.5 111.75 0 top
PR6024  0_0402_5%  [R_0402]  154.04 131.66 180 bottom
PR6025  1K_0402_1%  [R_0402]  153.81 133.58 270 top
PR6026  0_0402_5%  [R0402_0OHM]  196.69 110.26 0 bottom
PR6027  2.2K_0402_1%  [R_0402]  157.67 143.74 270 top
PR6028  2.2K_0402_1%  [R_0402]  158.56 143.74 270 top
PR6029  2K_0402_1%  [R_0402]  159.55 143.74 270 top
PR6030  100_0402_5%  [R_0402]  194.98 110.15 270 bottom
PR6033  100K_0402_5%  [R_0402]  160.44 143.74 270 top
PR6034  10K_0402_5%  [R_0402]  165.44 130.08 0 top
PR6035  0_0402_5%  [R0402_0OHM]  162.59 138.32 0 top
PR6036  20K_0402_1%  [R_0402]  158.41 133.58 270 top
PR6037  2.2_0603_1%  [R_0603]  162.78 143.87 180 top
PR6038  33K_0402_5%  [R_0402]  165.28 138.27 180 top
PR6039  6.19K_0402_1%  [R_0402]  162.85 133.77 270 top
PR6040  0_0402_5%  [R_0402]  161.08 133.58 270 top
PR6041  0_0402_5%  [R0402_0OHM]  162.59 140.99 0 top
PR6042  0_0402_5%  [R_0402]  158.46 133.39 270 bottom
PR6043  4.32K_0402_1%  [R_0402]  162.59 135.65 0 top
PR6044  10K_0402_5%  [R_0402]  156.63 133.58 270 top
PR6045  0_0402_5%  [R0402_0OHM]  162.59 140.1 0 top
PR6046  43K_0402_5%  [R_0402]  153.67 139.47 180 top
PR6047  36K_0402_5%  [R_0402]  153.67 140.36 180 top
PR6048  10K_0402_5%  [R_0402]  155.74 133.58 270 top
PR6050  10K_0402_5%  [R_0402]  157.52 133.58 270 top
PR6051  0_0402_5%  [R0402_0OHM]  159.3 132.67 90 top
PR6052  16.5K_0402_1%  [R_0402]  162.59 134.76 0 top
PR6053  0_0402_5%  [R0402_0OHM]  163.5 139.21 180 top
PR6054  0_0402_5%  [R_0402]  159.36 132.48 90 bottom
PR6056  8.2K_0402_5%  [R_0402]  152.69 140.74 0 bottom
PR6057  8.2K_0402_5%  [R_0402]  152.76 141.25 0 top
PR6058  0_0402_5%  [R_0402]  155.67 132.55 90 bottom
PR6059  0_0402_5%  [R_0402]  156.56 132.55 90 bottom
PR6060  0_0402_5%  [R0402_0OHM]  151.54 141.56 270 bottom
PR6061  100K_0402_5%  [R_0402]  160.19 132.67 90 top
PR6062  309_0402_1%  [R_0402]  164.36 134.71 0 top
PR6063  0_0402_5%  [R_0402]  157.53 132.48 90 bottom
PR6064  20.5K_0402_1%  [R_0402]  162.59 136.54 0 top
PR6069  0_0402_5%  [R0402_0OHM]  161.96 132.86 90 top
PR6070  0_0402_5%  [R0402_0OHM]  151.99 134.25 90 top
PR6100  0.005_2512_1%  [RL-3264-9W-R005-FNH_2512_2512]  117.22 101.32 180 top
PR6101  0.005_2512_1%  [RL-3264-9W-R005-FNH_2512_2512]  117.22 108.69 180 top
PR6102  0_0402_5%  [R_0402]  171.43 129.51 180 bottom
PR6103  10K_0402_1%  [R_0402]  173.19 129.31 0 top
PR6104  1K_0402_1%  [R_0402]  171.4 130.4 90 bottom
PR6105  0_0402_5%  [R_0402]  170.52 128.62 0 bottom
PR6106  2.2_0603_1%  [R_0603]  175.05 129.12 0 top
PR6107  2.2_0402_1%  [R_0402]  170.47 132.19 0 bottom
PR6108  2.2_0603_1%  [R_0603]  179.43 131.35 180 top
PR6109  0_0402_5%  [R_0402]  170.99 137.63 180 bottom
PR6110  1K_0402_1%  [R_0402]  170.96 139.46 90 bottom
PR6111  0_0402_5%  [R_0402]  170.08 138.52 0 bottom
PR6112  10K_0402_1%  [R_0402]  170.99 136.74 180 bottom
PR6113  2.2_0603_1%  [R_0603]  175.11 139.16 270 top
PR6114  2.2_0402_1%  [R_0402]  170.03 141.29 0 bottom
PR6115  2.2_0603_1%  [R_0603]  177.69 141.61 90 top
PR6116  0_0402_5%  [R_0402]  173.22 116.93 180 bottom
PR6117  10K_0402_1%  [R_0402]  174.09 115.29 270 bottom
PR6118  1K_0402_1%  [R_0402]  173.28 117.87 90 bottom
PR6119  0_0402_5%  [R_0402]  172.3 116.04 0 bottom
PR6120  2.2_0603_1%  [R_0603]  175.05 113.95 0 bottom
PR6121  2.2_0402_1%  [R_0402]  172.29 120.2 0 bottom
PR6122  2.2_0603_1%  [R_0603]  181.33 120.3 270 top
PU10V0  -  [RT8061AZQW_WDFN10_3X3]  120.72 95.77 270 bottom
PU18V00  -  [SY8286RAC_QFN20_3X3]  272.04 80.05 180 bottom
PU25V00  -  [RT9059GSP_SO8]  172.56 30.35 270 bottom
PU100  -  [SY8286RAC_QFN20_3X3]  251.82 42 270 top
PU200  RT8207PGQW_WQFN20_3X3  [RT8207PGQW_WQFN20_3X3-S]  110.79 65.63 0 top
PU300  -  [TPS51285BRUKR_QFN20_3X3]  82.83 42.02 180 top
PU700  BQ24780SRUYR_QFN28_4X4  [BQ24780RUYR_WQFN28_4X4-S]  35.74 40.52 270 top
PU800  -  [TPS51212DSCR_SON10_3X3]  236.31 56.72 270 top
PU4000  -  [SY8286RAC_QFN20_3X3]  123 101.89 0 bottom
PU5000  ISL95829AHRTZ-T_TQFN48_6X6  [ISL95855HRTZ-T_TQFN48_6X6-S]  134.85 140.93 0 top
PU5101  -  [SIC632CDT1GE3_POWERPAK31_5X5]  149.65 128.23 270 bottom
PU5102  -  [SIC632CDT1GE3_POWERPAK31_5X5]  141.05 128.04 270 bottom
PU5103  -  [SIC632CDT1GE3_POWERPAK31_5X5]  158.32 128.24 270 bottom
PU5201  -  [SIC632CDT1GE3_POWERPAK31_5X5]  117.79 118.18 0 bottom
PU5202  -  [SIC632CDT1GE3_POWERPAK31_5X5]  117.94 126.91 0 bottom
PU5203  -  [SIC531CDT1GE3_POWERPAK22_4X3]  167.5 126.87 270 bottom
PU6000  -  [UP9511PQGJ_VQFN40_5X5]  160.89 136.34 180 top
PU6100  -  [SIC632CDT1GE3_POWERPAK31_5X5]  173.05 129.92 0 bottom
PU6101  -  [SIC632CDT1GE3_POWERPAK31_5X5]  172.6 138.73 0 bottom
PU6102  -  [SIC632CDT1GE3_POWERPAK31_5X5]  174.58 117.4 0 bottom
Q12  L2N7002LT1G_SOT23-3  [2N7002K_SOT23-3]  85.04 65.37 90 bottom
Q13  L2N7002LT1G_SOT23-3  [2N7002K_SOT23-3]  308.17 47.53 90 top
QA1  -  [LN2306LT1G_SOT23-3]  334.73 25.57 90 top
QC5  -  [DMN65D8LDW-7_SOT363-6]  254.66 25.13 0 bottom
QE3  -  [L2N7002WT1G_SC-70-3]  120.46 29.26 90 bottom
QE4  -  [DMG2301U-7_SOT23-3]  115.86 27.99 0 bottom
QE5  -  [L2N7002WT1G_SC-70-3]  188.76 31.46 270 bottom
QE13  -  [L2N7002WT1G_SC-70-3]  126.99 29.37 180 bottom
QE19  -  [DMN65D8LDW-7_SOT363-6]  158.77 24.47 0 bottom
QE20  -  [DMN65D8LDW-7_SOT363-6]  221.45 58.29 180 top
QE21  DMN63D8LDW-7_SOT363-6  [DMN65D8LDW-7_SOT363-6]  224.61 56.34 0 top
QE23  -  [DMN65D8LDW-7_SOT363-6]  215.54 56.61 0 top
QE24  -  [DMN65D8LDW-7_SOT363-6]  280.19 7.97 0 top
QG2  -  [MESS138W-G_SOT323-3]  216.38 137.76 90 bottom
QG3  -  [MESS138W-G_SOT323-3]  261.48 125.82 90 bottom
QG4  -  [MESS138W-G_SOT323-3]  258.61 90.16 270 bottom
QG6  DMN53D0LDW-7 2N SOT363-6  [2N7002DW-7-F_SOT363-6]  198.6 72.48 0 bottom
QG7  DMN53D0LDW-7 2N SOT363-6  [2N7002DW-7-F_SOT363-6]  209.8 70.6 180 bottom
QG8  DMN61D9UDW-7 2N SOT363-6  [DMN65D8LDW-7_SOT363-6]  188.87 60.97 315 top
QG9  BSS138W 1N SOT-323-3  [BSS138W-7-F_SOT323-3]  202.09 60.35 270 top
QG23  DMN63D8LDW-7 2N SOT363-6  [DMN65D8LDW-7_SOT363-6]  208.7 81.21 0 top
QG502  DMN53D0LDW-7 2N SOT363-6  [2N7002DW-7-F_SOT363-6]  227.22 63.95 90 top
QG503  DMN53D0LDW-7_SOT363-6  [2N7002DW-7-F_SOT363-6]  217.43 62.45 0 top
QG504  DMN53D0LDW-7_SOT363-6  [2N7002DW-7-F_SOT363-6]  214.77 62.45 0 top
QG505  DMN53D0LDW-7_SOT363-6  [2N7002DW-7-F_SOT363-6]  212.1 62.45 0 top
QG509  DMN53D0LDW-7 2N SOT363-6  [2N7002DW-7-F_SOT363-6]  196.62 61.69 0 top
QG510  -  [MESS138W-G_SOT323-3]  203.75 73.88 0 bottom
QG511  -  [MESS138W-G_SOT323-3]  221.66 60.12 270 top
QG513  DMN53D0LDW-7_SOT363-6  [2N7002DW-7-F_SOT363-6]  241.32 74.53 0 bottom
QH4  -  [DMN65D8LDW-7_SOT363-6]  270.46 29.04 90 top
QH6  L2N7002LT1G_SOT23-3  [2N7002K_SOT23-3]  292.79 8.7 90 top
QP1  S TR METR3904W-G NPN SOT323-3  [MMST3904-7-F_SOT323-3]  333.1 57.56 270 top
QTH1  MMBT3904WH_SOT323-3  [MMST3904-7-F_SOT323-3]  186.73 123.54 0 top
QTH2  MMBT3904WH_SOT323-3  [MMST3904-7-F_SOT323-3]  239.88 71.53 270 bottom
QTH3  -  [DMN65D8LDW-7_SOT363-6]  96.1 73.18 0 top
QTPM1  ME2301DC-G_SOT23-3  [LP2301ALT1G_SOT23-3]  289.12 8.73 270 bottom
QV2  -  [L2N7002WT1G_SC-70-3]  82.91 35.08 180 bottom
QV11  SI3457BDV-T1-E3_TSOP6~D  [SI3457BDV-T1-E3_TSOP6]  88.12 39.7 270 bottom
QZ2  -  [LN2306LT1G_SOT23-3]  335.03 33.61 90 top
QZ13  -  [DMN65D8LDW-7_SOT363-6]  66.43 56.1 0 top
R1  1M_0402_5%  [R_0402]  68.05 54.12 90 top
R2  4.7K_0805_5%  [R_0805]  64.43 57.14 270 top
R3  1M_0402_5%  [R_0402]  65.34 59.19 0 top
R4  1M_0402_5%  [R_0402]  67.1 59.19 0 top
R5  1M_0402_5%  [R_0402]  67.17 55.02 180 top
R126  0_0402_5%  [R_0402-NPM]  222.94 30.52 180 bottom
R127  0_0402_5%  [R_0402-NPM]  222.94 31.41 180 bottom
RA1  0_0402_5%  [R0402_0OHM]  350.6 23.27 0 bottom
RA2  10K_0402_5%  [R_0402]  336.4 8.63 180 bottom
RA5  0_0402_5%  [R0402_0OHM]  338.04 13.68 0 top
RA7  0_0805_5%  [R0805_0OHM]  335.95 29.01 270 top
RA8  0_0603_5%  [R0603_0OHM]  340.84 14.51 180 bottom
RA9  0_0402_5%  [R0402_0OHM]  347.38 6.9 270 top
RA10  0_0805_5%  [R0805_0OHM]  337.73 29.01 270 top
RA11  100K_0402_5%  [R_0402]  350.99 17.36 180 top
RA12  0_0402_5%  [R0402_0OHM]  357.35 7.03 270 top
RA13  0_0402_5%  [R0402_0OHM]  353.8 19.85 0 top
RA14  0_0402_5%  [R0402_0OHM]  345.73 22.95 270 bottom
RA15  0_0402_5%  [R0402_0OHM]  353.16 23.33 45 top
RA16  0_0805_5%  [R0805_0OHM]  341.42 11.61 270 bottom
RA17  0_0402_5%  [R_0402]  345.71 8.37 225 top
RA18  0_0402_5%  [R_0402]  345.03 9.03 225 top
RA19  0_0402_5%  [R0402_0OHM]  342.81 15.41 270 top
RA22  200K_0402_5%  [R_0402]  341.86 14.71 270 top
RA23  100K_0402_5%  [R_0402]  338.13 25.36 180 top
RA24  100K_0402_5%  [R_0402]  339.88 13.68 0 top
RA27  33_0402_5%  [R_0402]  337.21 22.48 0 top
RA30  1K_0402_5%  [R_0402]  343.64 9.03 45 top
RA32  33_0402_5%  [R_0402]  337.66 19.19 0 top
RA33  10K_0402_5%  [R_0402]  343.64 10.32 225 top
RA42  2.2K_0402_5%  [R_0402]  345.48 13.8 90 bottom
RA43  2.2K_0402_5%  [R_0402]  344.53 13.8 90 bottom
RA44  10_0402_1%  [R_0402]  351.75 12.91 0 top
RA46  4.7K_0402_5%  [R_0402]  351.75 12.02 0 top
RA48  1K_0402_5%  [R_0402]  351.75 13.92 0 top
RA49  10_0402_1%  [R_0402]  351.71 10.25 180 top
RA51  1K_0402_5%  [R_0402]  349.91 9.3 0 top
RA53  4.7K_0402_5%  [R_0402]  351.71 11.14 180 top
RA56  0_0402_5%  [R0402_0OHM]  347.59 7.39 180 bottom
RA57  0_0603_5%  [R0603_0OHM]  331.98 9.21 90 top
RA58  0_0603_5%  [R_0603]  334.53 23 180 top
RC11  1K_0402_5%  [R_0402]  262.65 18.04 180 bottom
RD7  10K_0402_5%  [R_0402]  284.86 16.52 180 bottom
RD8  10K_0402_5%  [R_0402]  283.63 12.36 270 bottom
RD9  0_0402_5%  [R_0402]  284.05 9.64 0 bottom
RD31  0_0402_5%  [R0402_0OHM]  203.79 31.78 270 bottom
RD35  470_0402_1%  [R_0402]  204.7 31.79 270 bottom
RD58  0_0402_5%  [R0402_0OHM]  274.44 8.79 180 top
RD59  0_0402_5%  [R0402_0OHM]  283.96 15.44 0 bottom
RD62  0_0402_5%  [R_0402]  254.29 27.05 270 bottom
RE1  100K_0402_5%  [R_0402]  118.49 25.94 90 bottom
RE2  240_0402_1%  [R_0402]  113.65 30.24 180 bottom
RE3  47K_0402_5%  [R_0402]  193.18 31.68 270 bottom
RE4  100K_0402_1%  [R_0402]  191.85 31.66 270 bottom
RE7  1.5K_0402_5%  [R_0402]  156.38 22.96 270 bottom
RE9  1.5K_0402_5%  [R_0402]  157.27 22.96 270 bottom
RE12  0_0603_5%  [R0603_0OHM]  321.54 16.98 180 top
RE13  10K_0402_1%  [R_0402]  308.78 26.89 270 top
RE14  100K_0402_1%  [R_0402]  306.92 26.83 0 top
RE15  0_0603_5%  [R0603_0OHM]  311.06 7.84 180 bottom
RE16  0_0603_5%  [R0603_0OHM]  302.74 25.94 0 bottom
RE17  33_0402_5%  [R_0402]  317.59 22 0 top
RE20  1K_0402_5%  [R_0402]  303.32 20.93 270 bottom
RE21  1K_0402_5%  [R_0402]  317.59 15.84 0 top
RE22  100K_0402_5%  [R_0402]  302.43 20.93 270 bottom
RE23  10K_0402_5%  [R_0402]  318.25 10.95 180 top
RE24  4.7K_0402_5%  [R_0402]  318.5 13.93 180 top
RE25  100K_0402_5%  [R_0402]  321.35 18.12 180 top
RE27  100K_0402_5%  [R_0402]  315.13 26.27 270 top
RE29  100K_0402_5%  [R_0402]  295.83 19.65 180 top
RE30  100K_0402_5%  [R_0402]  315.18 10.41 180 bottom
RE31  100K_0402_5%  [R_0402]  301.47 23.35 270 bottom
RE33  100K_0402_5%  [R_0402]  311.48 16.32 0 bottom
RE34  10K_0402_1%  [R_0402]  302.95 13.74 180 bottom
RE35  10K_0402_1%  [R_0402]  302.03 11.84 0 bottom
RE36  300_0402_5%  [R_0402]  308.09 26.85 270 bottom
RE38  100K_0402_5%  [R_0402]  311.48 15.43 0 bottom
RE39  100K_0402_5%  [R_0402]  310.05 25.94 90 top
RE43  4.7K_0402_5%  [R_0402]  300.01 19.03 180 bottom
RE44  4.7K_0402_5%  [R_0402]  300.01 18.08 180 bottom
RE45  2.2K_0402_5%  [R_0402]  300.01 17.07 180 bottom
RE46  2.2K_0402_5%  [R_0402]  300.01 16.05 180 bottom
RE47  1K_0402_5%  [R_0402]  301.49 19.97 180 bottom
RE52  100K_0402_5%  [R_0402]  302.43 22.43 90 bottom
RE53  100K_0402_5%  [R_0402]  295.56 7.79 180 top
RE55  4.7K_0402_5%  [R_0402]  318.5 14.89 180 top
RE57  0_0402_5%  [R0402_0OHM]  318.5 18.95 180 top
RE58  0_0402_5%  [R0402_0OHM]  304.2 20.02 90 bottom
RE60  49.9_0402_1%  [R_0402]  326.94 11.45 90 bottom
RE61  0_0402_5%  [R0402_0OHM]  294.83 6.86 270 top
RE62  0_0402_5%  [R0402_0OHM]  306.88 7.97 180 bottom
RE63  10K_0402_5%  [R_0402]  321.98 12.36 270 bottom
RE64  10K_0402_5%  [R_0402]  320.02 12.36 270 bottom
RE65  100K_0402_5%  [R_0402]  321.03 12.36 270 bottom
RE66  0_0402_5%  [R0402_0OHM]  303.33 25.56 180 top
RE67  0_0603_5%  [R0603_0OHM]  306.05 20.73 0 bottom
RE68  0_0402_5%  [R0402_0OHM]  320.44 19.2 0 top
RE71  33_0402_5%  [R_0402]  302.83 35.31 90 bottom
RE73  0_0402_5%  [R0402_0OHM]  312.41 17.24 180 bottom
RE81  100K_0402_5%  [R_0402]  103.35 62.46 270 top
RE82  10K_0402_5%  [R_0402]  101.02 62.45 180 top
RE83  100K_0402_5%  [R_0402]  256.33 27.05 270 bottom
RE84  10K_0402_5%  [R_0402]  309.88 50.48 0 top
RE87  100K_0402_5%  [R_0402]  125.26 28.93 270 bottom
RE93  0_0603_5%  [R0603_0OHM]  130.34 27.46 180 bottom
RE100  10K_0402_5%  [R_0402]  85.97 62.64 180 bottom
RE101  10K_0402_5%  [R_0402]  309.92 48.11 270 top
RE104  0_0603_5%  [R0603_0OHM]  101.58 63.72 180 top
RE105  0_0603_5%  [R0603_0OHM]  309.38 49.21 0 top
RE106  0_0402_5%  [R_0402]  301.36 25.56 180 top
RE109  0_0402_5%  [R0402_0OHM]  325.92 12.36 270 bottom
RE110  0_0402_5%  [R0402_0OHM]  324.91 12.36 270 bottom
RE111  0_0402_5%  [R0402_0OHM]  323.89 12.36 270 bottom
RE112  0_0402_5%  [R0402_0OHM]  322.94 12.36 270 bottom
RE113  100K_0402_5%  [R_0402]  296.01 21.49 180 top
RE114  100K_0402_5%  [R_0402]  311.37 10.7 0 bottom
RE115  0_0805_5%  [R0805_0OHM]  351.49 38.06 0 bottom
RE116  0_0402_5%  [R0402_0OHM]  314.49 21.83 0 bottom
RE118  10K_0402_5%  [R_0402]  319.06 12.36 270 bottom
RE119  100K_0402_5%  [R_0402]  317.86 10.77 270 bottom
RE120  100K_0402_5%  [R_0402]  117.48 29.71 270 bottom
RE121  10K_0402_5%  [R_0402]  89 66.33 270 bottom
RE122  10K_0402_5%  [R_0402]  304.14 48.05 270 top
RE123  100K_0402_5%  [R_0402]  156.44 29.29 90 bottom
RE124  100K_0402_1%  [R_0402]  307.67 22.46 180 bottom
RE125  10K_0402_1%  [R_0402]  305.74 22.46 90 bottom
RE126  33_0402_5%  [R_0402]  303.79 35.31 90 bottom
RE127  33_0402_5%  [R_0402]  301.54 41.86 90 top
RE128  33_0402_5%  [R_0402]  304.69 35.3 90 bottom
RE129  33_0402_5%  [R_0402]  302.49 41.86 90 top
RE130  0_0402_5%  [R0402_0OHM]  293.96 6.86 270 top
RE131  0_0402_5%  [R0402_0OHM]  297.41 22.38 180 top
RE132  0_0402_5%  [R_0402]  308.76 9.81 90 bottom
RE133  0_0402_5%  [R0402_0OHM]  292.74 12.06 270 top
RE134  0_0402_5%  [R0402_0OHM]  312.28 9.74 180 bottom
RE135  0_0402_5%  [R0402_0OHM]  317.34 12.98 0 top
RE138  0_0402_5%  [R0402_0OHM]  300.52 22.43 90 bottom
RE139  2.2K_0402_5%  [R_0402]  317.59 18 0 top
RE140  2.2K_0402_5%  [R_0402]  317.59 19.9 0 top
RE141  10K_0402_5%  [R_0402]  297.3 7.79 180 top
RE143  100K_0402_5%  [R_0402]  302.95 9.93 180 bottom
RE144  0_0402_5%  [R_0402]  297.22 8.97 90 bottom
RE145  0_0402_5%  [R_0402]  296.33 8.97 90 bottom
RE146  10K_0402_5%  [R_0402]  227.03 59.01 270 top
RE147  300_0402_5%  [R_0402]  306.05 25.94 90 top
RE148  0_0402_5%  [R_0402]  316.45 23.68 270 top
RE149  0_0402_5%  [R_0402]  290.97 12.06 270 top
RE150  100K_0402_5%  [R_0402]  291.86 12.06 270 top
RE151  100K_0402_5%  [R_0402]  301.12 15.1 0 bottom
RE152  1M_0402_5%  [R_0402]  227.02 57.26 270 top
RG16  100K_0201_5%  [R_0201]  205.18 78.01 180 top
RG17  1.8K_0402_5%  [R_0402]  201.08 70.56 90 bottom
RG18  1.8K_0402_5%  [R_0402]  197.4 72.62 270 bottom
RG19  1.8K_0402_5%  [R_0402]  203.3 84.92 0 top
RG20  1.8K_0402_5%  [R_0402]  205.18 84.12 90 top
RG21  10K_0201_5%  [R_0201]  196.34 74.07 0 bottom
RG22  10K_0201_5%  [R_0201]  206.74 81.47 270 top
RG23  2.49K_0402_1%  [R_0402]  196.69 109.38 0 bottom
RG24  100K_0201_5%  [R_0201]  205.4 81.6 270 top
RG26  10K_0201_5%  [R_0201]  197.78 90.62 270 bottom
RG37  1K_0402_1%  [R_0402]  205.86 93.31 180 top
RG47  10K_0402_5%  [R_0402]  230.67 138.15 270 top
RG48  10K_0402_5%  [R_0402]  200.62 137.18 0 top
RG49  10K_0402_5%  [R_0402]  259.58 110.01 180 top
RG50  10K_0402_5%  [R_0402]  233.59 138.34 270 top
RG51  10K_0402_5%  [R_0402]  257.17 78.38 180 top
RG52  10K_0402_5%  [R_0402]  257.73 106.27 270 top
RG53  10K_0402_5%  [R_0402]  200.68 134.96 0 top
RG54  10K_0402_5%  [R_0402]  230.54 135.36 270 top
RG55  10K_0402_5%  [R_0402]  233.59 134.72 270 top
RG56  10K_0402_5%  [R_0402]  257.29 109.74 90 top
RG57  10K_0402_5%  [R_0402]  256.36 107.15 0 top
RG58  10K_0402_5%  [R_0402]  256.26 79.34 0 top
RG59  10_0402_1%  [R_0402]  231.9 76.29 180 bottom
RG60  1.8K_0402_1%  [R_0402]  221.34 74.57 0 bottom
RG61  1.8K_0402_1%  [R_0402]  221.34 75.46 0 bottom
RG62  10_0402_1%  [R_0402]  231.9 74.95 180 bottom
RG64  10_0402_1%  [R_0402]  231.96 73.05 180 bottom
RG65  10K_0402_1%  [R_0402]  222.45 72.78 90 bottom
RG66  10_0402_1%  [R_0402]  231.96 72.1 180 bottom
RG67  40.2_0402_1%  [R_0402]  226.3 109.19 270 top
RG68  40.2_0402_1%  [R_0402]  226.45 110.06 90 top
RG69  60.4_0402_1%  [R_0402]  226.3 111.84 90 top
RG70  10K_0402_5%  [R_0402]  218.53 71.02 0 bottom
RG71  10K_0402_5%  [R_0402]  203.37 59.9 90 top
RG74  10K_0402_5%  [R_0402]  187.36 82.95 90 bottom
RG75  33_0402_5%~D  [R_0402]  193.64 80.1 0 bottom
RG76  33_0402_5%~D  [R_0402]  190.22 83.86 270 bottom
RG77  33_0402_5%~D  [R_0402]  193.64 81.05 0 bottom
RG78  100K_0402_1%  [R_0402]  201.98 78.46 270 top
RG79  100K_0402_1%  [R_0402]  198.68 77.55 90 top
RG80  100K_0402_1%  [R_0402]  198.68 74.4 270 bottom
RG81  100K_0402_1%  [R_0402]  197.72 74.4 270 bottom
RG82  100K_0402_1%  [R_0402]  198.68 81.18 270 top
RG83  100K_0402_1%  [R_0402]  202.87 78.46 270 top
RG84  100K_0402_1%  [R_0402]  194.56 77.18 180 bottom
RG85  100K_0402_1%  [R_0402]  189.28 83.86 270 bottom
RG86  100K_0402_1%  [R_0402]  194.56 78.19 180 bottom
RG87  100K_0402_1%  [R_0402]  193.65 76.29 0 bottom
RG88  100K_0402_1%  [R_0402]  191.11 82.95 90 bottom
RG89  100K_0402_1%  [R_0402]  193.65 79.15 0 bottom
RG90  100K_0402_1%  [R_0402]  201.02 77.55 90 top
RG91  100K_0402_1%  [R_0402]  199.69 78.46 270 top
RG92  100K_0402_1%  [R_0402]  198.48 76.18 270 bottom
RG93  100K_0402_1%  [R_0402]  197.4 76.24 270 bottom
RG94  100K_0402_1%  [R_0402]  199.76 82.04 180 top
RG95  100K_0402_1%  [R_0402]  203.82 77.55 90 top
RG98  100K_0402_5%~D  [R_0402]  196.51 76.69 270 bottom
RG99  10M_0402_5%  [R_0402]  197.6 84.81 270 bottom
RG101  10K_0402_5%  [R_0402]  202.47 83.46 0 top
RG102  40.2_0402_1%  [R_0402]  217.46 134.01 180 top
RG103  40.2_0402_1%  [R_0402]  212.82 133.18 0 top
RG104  1K_0402_1%  [R_0402]  231.49 135.36 270 top
RG105  1K_0402_1%  [R_0402]  198.92 135.84 90 top
RG106  1K_0402_1%  [R_0402]  221.71 135.61 270 top
RG107  1K_0402_1%  [R_0402]  206.41 136.54 90 top
RG108  121_0402_1%  [R_0402]  217.89 135.8 270 top
RG109  121_0402_1%  [R_0402]  212 135.97 90 top
RG110  549_0402_1%  [R_0402]  213.01 137.07 270 bottom
RG111  931_0402_1%  [R_0402]  215.17 136.11 180 bottom
RG112  1.33K_0402_1%  [R_0402]  213.08 135.29 270 bottom
RG113  40.2_0402_1%  [R_0402]  256.78 121.82 90 top
RG114  40.2_0402_1%  [R_0402]  247.94 133.18 0 bottom
RG115  1K_0402_1%  [R_0402]  258.43 108.03 270 top
RG116  1K_0402_1%  [R_0402]  233.59 135.65 90 top
RG117  1K_0402_1%  [R_0402]  257.98 113.31 180 top
RG118  1K_0402_1%  [R_0402]  240.89 135.84 90 top
RG119  121_0402_1%  [R_0402]  258.73 121.63 0 top
RG120  121_0402_1%  [R_0402]  247.75 136.35 90 bottom
RG121  549_0402_1%  [R_0402]  260.22 122.33 180 bottom
RG122  931_0402_1%  [R_0402]  260.22 123.21 180 bottom
RG123  1.33K_0402_1%  [R_0402]  258.38 124.1 180 bottom
RG124  40.2_0402_1%  [R_0402]  256.52 87.08 90 top
RG125  40.2_0402_1%  [R_0402]  256.07 91.97 180 top
RG126  1K_0402_1%  [R_0402]  256.73 74.97 0 top
RG127  1K_0402_1%  [R_0402]  256.27 105.36 90 top
RG128  1K_0402_1%  [R_0402]  256.96 80.73 0 top
RG129  1K_0402_1%  [R_0402]  256.32 97.94 0 top
RG130  121_0402_1%  [R_0402]  256.7 84.73 0 top
RG131  121_0402_1%  [R_0402]  256.67 93.82 0 top
RG132  549_0402_1%  [R_0402]  254.48 91.15 0 bottom
RG133  931_0402_1%  [R_0402]  257.3 91.15 180 bottom
RG134  1.33K_0402_1%  [R_0402]  256.38 89.37 0 bottom
RG156  10K_0402_5%  [R_0402]  188.75 59.65 135 top
RG157  0_0201_5%  [R_0201]  202.22 76.39 270 bottom
RG159  1.8K_0402_1%  [R_0402]  206.59 70.51 0 bottom
RG160  0_0201_5%  [R_0201]  222.92 63.24 90 top
